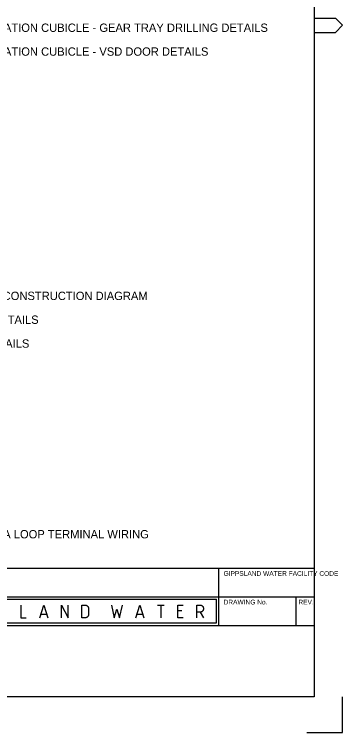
# Model space of a CAD drawing. Extents: x 0 to 841, y 0 to 594.
# Drawn here: x 703.2 to 841, y 0 to 301.4 of the extents above; entities that cross this region are included whole.
import ezdxf

# ---------------------------------------------------------------- set-up
doc = ezdxf.new("R2010")
doc.units = 0
doc.layers.add('A1BORDER', color=7, linetype='Continuous')
doc.layers.add('Level 1', color=7, linetype='Continuous')

msp = doc.modelspace()

# ---------------------------------------------------------------- linework, layer by layer
at = {"layer": 'A1BORDER'}
for p, q in [((829, 581), (829, 15)), ((829, 299.76), (838, 299.76)), ((838, 299.76), (841, 296.76)), ((838, 293.76), (841, 296.76)), ((829, 293.76), (838, 293.76)), ((592.5, 69), (829, 69)), ((789, 45), (789, 69)), ((28, 57), (829, 57)), ((637, 56), (788, 56)), ((788, 46), (788, 56)), ((821.5, 45), (821.5, 57)), ((663, 46), (788, 46)), ((664, 45), (829, 45)), ((829, 15), (28, 15)), ((829, 15), (829, 15)), ((841, 0), (841, 15)), ((826, 0), (841, 0))]:
    msp.add_line(p, q, dxfattribs=at)
for points in [[(705.96, 53.54), (705.96, 48.16), (708.23, 48.16)], [(713.91, 48.16), (715.61, 53.54), (717.32, 48.16)], [(722.99, 48.16), (722.99, 53.54), (725.83, 48.16), (725.83, 53.54)], [(731.52, 48.16), (731.52, 53.54), (732.94, 53.54), (733.06, 53.54), (733.18, 53.52), (733.3, 53.49), (733.42, 53.45), (733.53, 53.4), (733.64, 53.34), (733.75, 53.27), (733.84, 53.19), (733.94, 53.1), (734.02, 53), (734.09, 52.9), (734.16, 52.79), (734.22, 52.67), (734.27, 52.56), (734.31, 52.43), (734.33, 52.31), (734.35, 52.18), (734.36, 52.05), (734.36, 49.66), (734.35, 49.52), (734.33, 49.39), (734.31, 49.27), (734.27, 49.14), (734.22, 49.02), (734.16, 48.91), (734.09, 48.8), (734.02, 48.7), (733.94, 48.6), (733.84, 48.51), (733.75, 48.43), (733.64, 48.36), (733.53, 48.3), (733.42, 48.25), (733.3, 48.21), (733.18, 48.18), (733.06, 48.16), (732.94, 48.16), (731.52, 48.16)], [(744.01, 53.54), (745.14, 48.16), (746.28, 51.75), (747.41, 48.16), (748.55, 53.54)], [(754.22, 48.16), (755.92, 53.54), (757.63, 48.16)], [(763.31, 53.54), (766.15, 53.54)], [(764.73, 53.54), (764.73, 48.16)], [(774.09, 48.16), (771.82, 48.16), (771.82, 53.54), (774.09, 53.54)], [(779.78, 48.16), (779.78, 53.54), (781.2, 53.54), (781.32, 53.54), (781.44, 53.52), (781.56, 53.49), (781.68, 53.45), (781.79, 53.4), (781.9, 53.34), (782.01, 53.27), (782.1, 53.19), (782.2, 53.1), (782.28, 53), (782.35, 52.9), (782.42, 52.79), (782.48, 52.67), (782.53, 52.56), (782.56, 52.43), (782.59, 52.31), (782.61, 52.18), (782.61, 52.05), (782.61, 51.91), (782.59, 51.78), (782.56, 51.66), (782.53, 51.53), (782.48, 51.42), (782.42, 51.3), (782.35, 51.19), (782.28, 51.09), (782.2, 50.99), (782.1, 50.9), (782.01, 50.82), (781.9, 50.75), (781.79, 50.69), (781.68, 50.64), (781.56, 50.6), (781.44, 50.57), (781.32, 50.55), (781.2, 50.55), (779.78, 50.55)], [(714.48, 49.66), (716.75, 49.66)], [(754.79, 49.66), (757.06, 49.66)], [(773.53, 51.15), (771.82, 51.15)], [(781.2, 50.55), (782.61, 48.16)]]:
    msp.add_lwpolyline(points, dxfattribs=at)

# ---------------------------------------------------------------- texts
for s, p in [('GIPPSLAND WATER FACILITY CODE', (791.03, 65.77)), ('DRAWING No.', (791.03, 53.77)), ('REV.', (822.43, 53.77))]:
    msp.add_text(s, height=2, dxfattribs=at).set_placement(p)
at = {"layer": 'Level 1'}
for s, height, p in [('PUMP STATION 7.5kW TO 22kW (VSD) - DIRECT METERED - BACK TO BACK / SIDE BY SIDE - PUMP STATION CUBICLE - GEAR TRAY DRILLING DETAILS', 3.49998, (470, 294)), ('PUMP STATION 7.5kW TO 22kW (VSD) - DIRECT METERED - BACK TO BACK / SIDE BY SIDE - PUMP STATION CUBICLE - VSD DOOR DETAILS', 3.49998, (470, 284)), ('PUMP STATION 7.5kW TO 22kW (VSD) - DIRECT METERED - PUMP WELL WASHER SOLENOID CAGE - CONSTRUCTION DIAGRAM', 3.49998, (470, 181.5)), ('PUMP STATION 7.5kW TO 22kW (VSD) - DIRECT METERED - BACK TO BACK CUBICLE - PUMP WELL DETAILS', 3.5, (470, 171.5)), ('PUMP STATION 7.5kW TO 22kW (VSD) - DIRECT METERED - SIDE BY SIDE CUBICLE - PUMP WELL DETAILS', 3.5, (470, 161.5)), ('STANDARD DRAWINGS - INSTRUMENTATION & CONTROL - STANDARD WIRING COLOUR CODING - mA LOOP TERMINAL WIRING', 3.49998, (470, 81.5))]:
    msp.add_text(s, height=height, dxfattribs=at).set_placement(p)

doc.saveas('drawing.dxf')
